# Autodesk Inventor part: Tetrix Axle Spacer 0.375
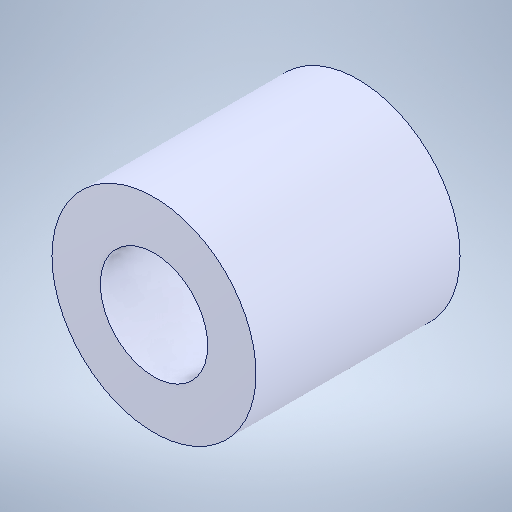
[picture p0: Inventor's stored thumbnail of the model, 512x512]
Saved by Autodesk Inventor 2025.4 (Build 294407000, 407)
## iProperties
Created: 2021-10
Part Number: Tetrix Axle Spacer 0.375
Material: Genérico
Document SubType Name: Modeling
Designer: usuario
Density: 1 g/cm^3
Appearance: Valor por defecto
Author: usuario
Sending System: SolidWorks 2016
Last Author: LENOVO
Last Saved: 2021-10-23
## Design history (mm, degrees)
feature "Revolve1"
node "Plane1"
node "Sólido1"
